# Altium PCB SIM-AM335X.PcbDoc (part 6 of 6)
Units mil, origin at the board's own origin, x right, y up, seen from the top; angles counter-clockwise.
Board outline 4041.51 x 2715.24 mil, 2 copper layers (Top Layer, Bottom Layer); 172 components, 190 nets, 855 pads, 317 vias.
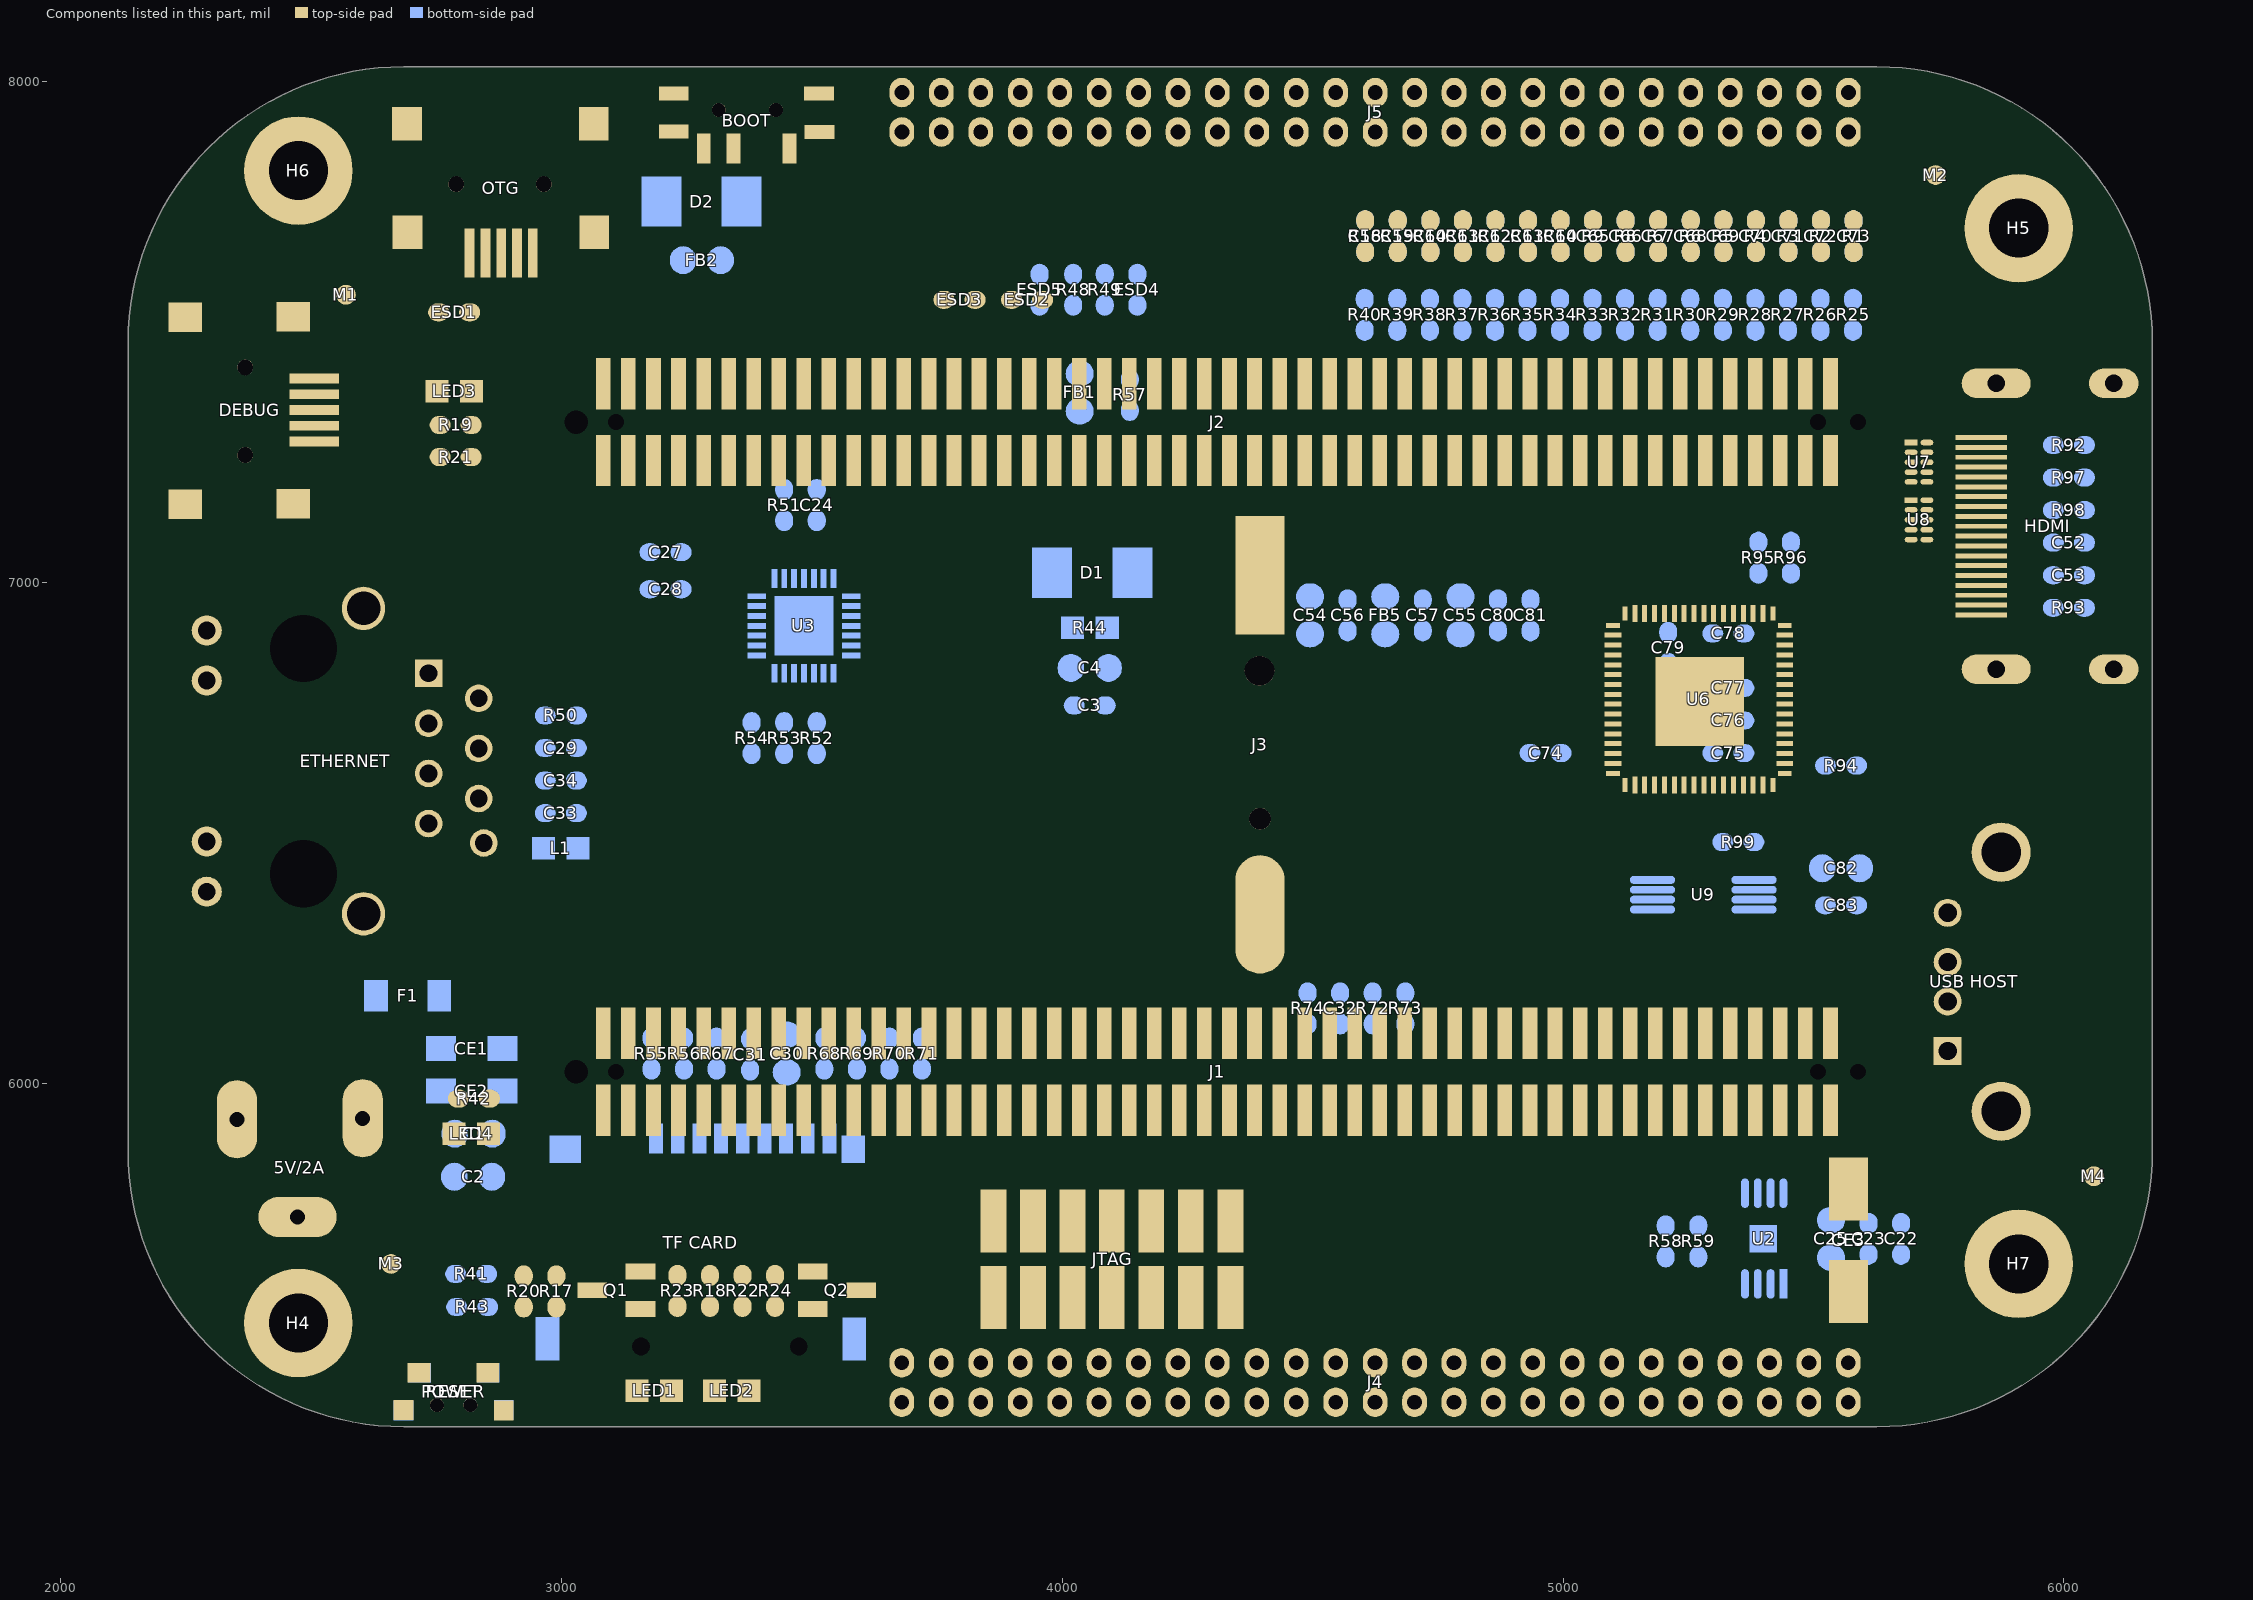
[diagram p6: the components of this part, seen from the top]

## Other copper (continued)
Bottom Layer:
  rectangle net USB_5V: 5459.68,5767.06 5477,5792
  rectangle net USB_5V: 5444,5763 5463,5809
  rectangle net VDD_5V: 2726.5,5780 2823.5,6208
  rectangle net VDD_IN: 2570,5933 2637,6207
  rectangle net GND_EARTH: 6109,6808 6156,7422
  rectangle net VDD_5V: 2811,6163 3095,6208
  pour cut-out: 5427,5812 5427,5752 5444,5752 5439.63,5756.37 5439.63,5802.76 5436.24,5802.76
  pour cut-out: 2137,6960.93 2137.93,6960 2914.92,6960 2914.92,6327.07 2133,6327.07 2133,6961 2135,6963 2135,6962

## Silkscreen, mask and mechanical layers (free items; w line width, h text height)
Top Overlay:
  drawing of 2291 lines, arcs and shapes, not listed
  text "2" at 3589,7967 h30
  text "50" at 5633,7967 h30
  text "49" at 5633,7882 h30
  text "1" at 3596,7881 h30
  text "SIM-AM335X_V2.0" at 3624,7713 h100
  text "NAND" at 3415,7711 h30
  text "SD" at 3250,7709 h30
  text "2" at 3073,7482 h30
  text "10" at 3262,7482 h30
  text "20" at 3509,7482 h30
  text "30" at 3758,7482 h30
  text "40" at 4004,7482 h30
  text "50" at 4259,7482 h30
  text "60" at 4518,7482 h30
  text "70" at 4767,7482 h30
  text "80" at 5020,7482 h30
  text "90" at 5268,7482 h30
  text "100" at 5504,7482 h30
  text "19" at 3510,7130 h30
  text "29" at 3759,7130 h30
  text "39" at 4008,7130 h30
  text "49" at 4254,7130 h30
  text "69" at 4759,7130 h30
  text "79" at 5008,7130 h30
  text "89" at 5264,7130 h30
  text "99" at 5511,7130 h30
  text "59" at 4508,7127 h30
  text "1" at 3078,7125 h30
  text "9" at 3275,7125 h30
  text "JLCJLCJLCJLC" at 2372,6470 h31.5 r90
  text "2" at 3075,6187 h30
  text "10" at 3260,6185 h30
  text "20" at 3505,6185 h30
  text "30" at 3761,6185 h30
  text "40" at 4010,6185 h30
  text "60" at 4512,6185 h30
  text "70" at 4760,6185 h30
  text "80" at 5010,6185 h30
  text "90" at 5260,6185 h30
  text "100" at 5495,6185 h30
  text "50" at 4258,6175 h30
  text "1" at 3081,5831 h30
  text "9" at 3270,5831 h30
  text "19" at 3515,5830 h30
  text "29" at 3761,5830 h30
  text "39" at 4010,5830 h30
  text "49" at 4258,5830 h30
  text "59" at 4512,5830 h30
  text "69" at 4760,5830 h30
  text "79" at 5010,5830 h30
  text "89" at 5260,5830 h30
  text "99" at 5462,5830 h30
  text "14" at 4385,5725 h30
  text "2" at 3792,5720 h30
  text "1" at 3798,5560 h30
  text "13" at 4385,5560 h30
  text "2" at 3595,5430 h30
  text "50" at 5633,5430 h30
  text "1" at 3601,5350 h30
  text "49" at 5633,5350 h30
